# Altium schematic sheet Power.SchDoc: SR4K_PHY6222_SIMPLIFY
size A4; Revision: V1.2; SheetNumber: 4; SheetTotal: 5
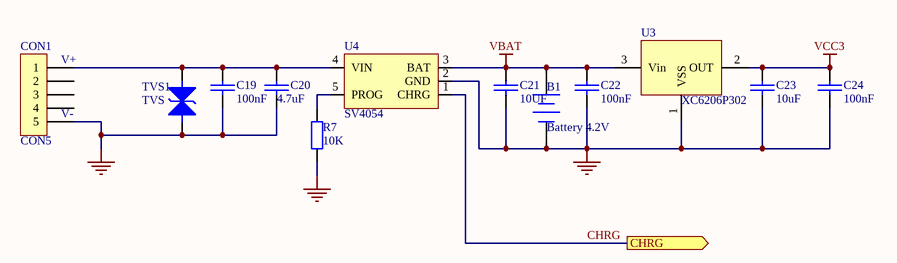
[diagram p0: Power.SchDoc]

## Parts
B1  Battery 4.2V  [JP2S]
C19  100nF  [0603]
C20  4.7uF  [0603]
C21  10UF  [0603]
C22  100nF  [0603]
C23  10uF  [0603]
C24  100nF  [0603]
CON1  CON5
R7  10K  [AXIAL-0.4]
TVS1  TVS  [SOD-123]
U3  XC6206P302  [SOT-23]
U4  SV4054  [SOT-25]

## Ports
CHRG (out)

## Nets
GND: B1.2(-) C19.1 C20.1 C21.1 C22.1 C23.1 C24.1 CON1.5 R7.1 TVS1.1 U3.1(VSS) U4.2(GND)
VBAT: B1.1(+) C21.2 C22.2 U3.3(Vin) U4.3(BAT)
VCC3: C23.2 C24.2 U3.2(OUT)
CHRG: U4.1(CHRG) ; port CHRG
NetC19_2: C19.2 C20.2 CON1.1 TVS1.2 U4.4(VIN)
NetR7_2: R7.2 U4.5(PROG)

Not connected (* = marked no-connect by the designer): CON1 2 3 4

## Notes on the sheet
- (near CON1) V+
- (near CON1) V-

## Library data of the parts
B1 = Battery: Multicell Battery
C19-C24 = CAP: Capacitor
CON1 = CON5: Connector
R7 = Res2: 1%@100mA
